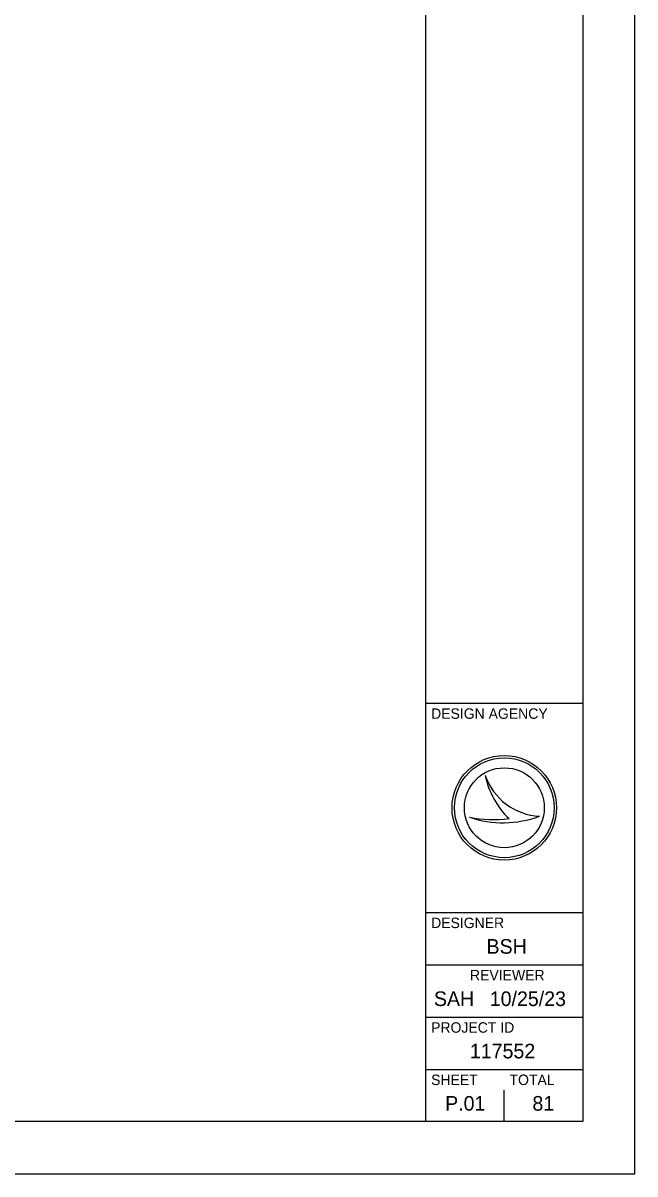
# Model space of a CAD drawing. Extents: x 0 to 34, y 0 to 22.
# Drawn here: x 28.15 to 34, y 0 to 11 of the extents above; entities that cross this region are included whole.
import ezdxf

# ---------------------------------------------------------------- set-up
doc = ezdxf.new("R2010")
doc.units = 0
for name, color, linetype in [('SH_Border', 7, 'Continuous'), ('SH_Cut_Line', 7, 'Continuous'), ('SH_Data', 7, 'Continuous')]:
    doc.layers.add(name, color=color, linetype=linetype)

msp = doc.modelspace()

# ---------------------------------------------------------------- linework, layer by layer
at = {"layer": 'SH_Border'}
for p, q in [((32, 0.5), (32, 21.5)), ((32, 4.5), (33.5, 4.5)), ((32, 2.5), (33.5, 2.5)), ((32, 2), (33.5, 2)), ((32, 1.5), (33.5, 1.5)), ((32, 1), (33.5, 1))]:
    msp.add_line(p, q, dxfattribs=at)
msp.add_lwpolyline([(1.5, 21.5), (33.5, 21.5), (33.5, 0.5), (1.5, 0.5)], close=True, dxfattribs=at)
at = {"layer": 'SH_Cut_Line'}
msp.add_lwpolyline([(0, 0), (34, 0), (34, 22), (0, 22)], close=True, dxfattribs=at)
at = {"layer": 'SH_Data'}
for p, q in [((32.567, 3.81), (32.567, 3.81)), ((32.75, 3.5), (32.75, 3.5)), ((33.087, 3.419), (33.087, 3.419)), ((32.417, 3.41), (32.417, 3.41)), ((32.75, 0.5), (32.75, 0.8)), ((32.375, 0.675), (32.375, 0.675))]:
    msp.add_line(p, q, dxfattribs=at)
for radius in [0.5, 0.477, 0.477, 0.382]:
    msp.add_circle((32.75, 3.5), radius, dxfattribs=at)
for centre, radius, start, end in [((33.116, 3.998), 0.58, 198.9257, 198.9319), ((33.347, 3.97), 0.796, 191.6379, 191.6421), ((33.116, 3.998), 0.58, 198.9319, 267.1657), ((33.347, 3.97), 0.796, 191.6421, 226.0947), ((32.739, 4.37), 1.013, 251.4576, 290.0832), ((32.648, 4.654), 1.266, 259.4964, 259.4995), ((32.739, 4.37), 1.013, 251.4527, 251.4576), ((32.648, 4.654), 1.266, 259.4995, 276.6672)]:
    msp.add_arc(centre, radius, start, end, dxfattribs=at)

# ---------------------------------------------------------------- texts
for s, height, p in [('DESIGN AGENCY', 0.1, (32.05, 4.35)), ('DESIGNER', 0.1, (32.05, 2.35)), ('BSH', 0.14, (32.58, 2.105)), ('REVIEWER', 0.1, (32.422, 1.85)), ('SAH', 0.14, (32.077, 1.605)), ('10/25/23', 0.14, (32.611, 1.605)), ('PROJECT ID', 0.1, (32.05, 1.35)), ('117552', 0.14, (32.421, 1.105)), ('SHEET', 0.1, (32.05, 0.85)), ('TOTAL', 0.1, (32.8, 0.85)), ('P.01', 0.14, (32.184, 0.605)), ('81', 0.14, (33.019, 0.605))]:
    msp.add_text(s, height=height, dxfattribs=at).set_placement(p)

doc.saveas('drawing.dxf')
